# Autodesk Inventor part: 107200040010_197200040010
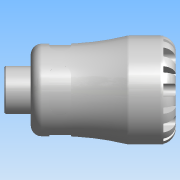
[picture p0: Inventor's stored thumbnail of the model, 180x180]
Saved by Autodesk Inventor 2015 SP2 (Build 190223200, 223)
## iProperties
Created: 2016-12
Part Number: 107200040010_197200040010
Material: PVC-Piping
Description: PLASSON MALE INTEGRAL BRASS THREAD 40X1" SERIES 1
Document SubType Name: Modeling
Designer: KIM
Mass: 61.7504 g
Surface Area: 140.097 cm^2
Volume: 44.1074 cm^3
Density: 1.4 g/cm^3
Appearance: Smooth - White
Author: KIM
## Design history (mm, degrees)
derived "1072.ipt"
feature "Solid1::1072.ipt"
tag "TaggingFeature1"
body "Solid1"
other parameters: "d1" = 30.66, "d6" = 73, "d8" = 59.5, "d13" = 8, "d14" = 8, "d15" = 0, "d17" = 360 deg, "d19" = 8 deg, "d20" = 0.8, "d21" = 0.8, "d22" = 8 deg, "d24" = 0, "d26" = 360 deg, "d32" = 7, "d33" = 7, "d34" = 30.931, "d38" = 17, "d39" = 0.92793, "d42" = 14, "d43" = 9.2, "d45" = 15.68, "d46" = 0, "d59" = 360 deg, "d61" = 11.9, "d62" = 0.8, "d64" = 0, "d65" = 0.7, "d68" = 5.71429, "l_" = 73, "R_" = 30.931, "l_2" = 17, "d9" = 10
